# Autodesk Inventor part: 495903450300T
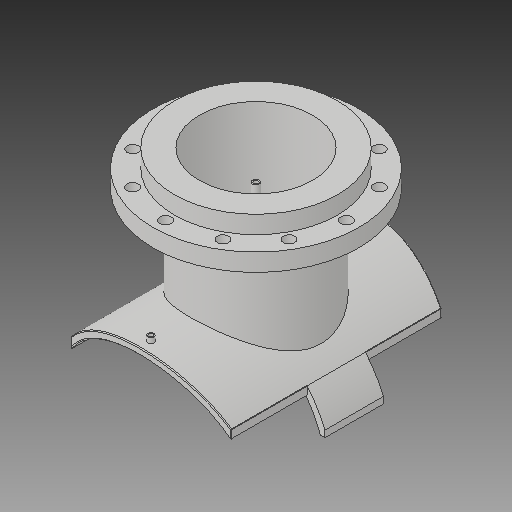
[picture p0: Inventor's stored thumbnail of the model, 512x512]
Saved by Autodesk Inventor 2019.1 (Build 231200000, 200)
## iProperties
Created: 2017-10
Part Number: 495903450300T
Material: Generic
Description: PLASSON FLANGED BRANCH SADDLE 450X300
Document SubType Name: Modeling
Designer: KIM
Mass: 2339.99 g
Surface Area: 3251.55 cm^2
Volume: 2339.99 cm^3
Density: 1 g/cm^3
Appearance: Default
Author: KIM
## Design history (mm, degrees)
derived "495904_495903.ipt"
feature "Solid1::495904_495903.ipt"
feature "Solid2::495904_495903.ipt"
tag "TaggingFeature1"
body "Solid1"
other parameters: "d1" = 15, "d2" = 364.5, "d4" = 0, "d6" = 132.5, "d7" = 0, "d12" = 250.6, "d13" = 14, "d14" = 238.5, "d16" = 5 deg, "d18" = 4, "d19" = 14, "d20" = 0, "d21" = 3, "d22" = 0, "d23" = 515, "d36" = 238.5, "d38" = 0, "d39" = 2, "d41" = 257, "d43" = 467, "d46" = 296, "d47" = 16, "d48" = 10.4, "d49" = 192.5, "d51" = 459, "d53" = 0, "d54" = 26, "d55" = 205, "d57" = 0, "d59" = 360 deg, "d63" = 0, "d66" = 275, "d67" = 15, "d68" = 137.5, "d70" = 0, "d71" = 2, "d72" = 405, "B_" = 405, "H_" = 275, "x_" = 15, "D_" = 16, "DN_" = 257, "D_1" = 467, "s_" = 26
